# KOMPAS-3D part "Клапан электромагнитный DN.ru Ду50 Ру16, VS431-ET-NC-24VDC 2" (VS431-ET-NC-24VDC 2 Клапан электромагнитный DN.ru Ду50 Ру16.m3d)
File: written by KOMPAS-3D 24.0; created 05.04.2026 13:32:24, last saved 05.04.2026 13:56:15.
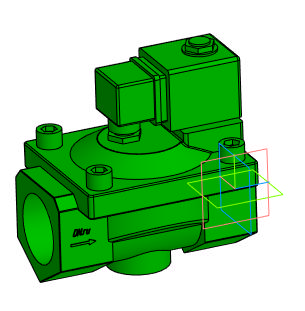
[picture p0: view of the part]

Document properties: Автор: artio; Полное имя файла: C:\Users\artio\OneDrive\Рабочий стол\Клапан электромагнитный DN.ru\VS431\VS431-ET-NC\VS431-ET-NC-24VDC\Ду50\VS431-ET-NC-24VDC 2 Клапан электромагнитный DN.ru Ду50 Ру16.m3d

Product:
- Body: Тело 1  | qty 1
    Масса: 6.703651
- Part/product: Клапан электромагнитный DN.ru Ду50 Ру16  | designation VS431-ET-NC-24VDC 2
    Масса: 3.341
    Раздел спецификации: Прочие изделия
    Примечание: D130-04745
    additional columns: ef56311e-7521-43dc-8291-0e6108b3d81d; artio; c; Шероховатость не задана; Да

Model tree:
1. Операция без истории:1

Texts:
  VS431-ET-NC-24VDC 2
